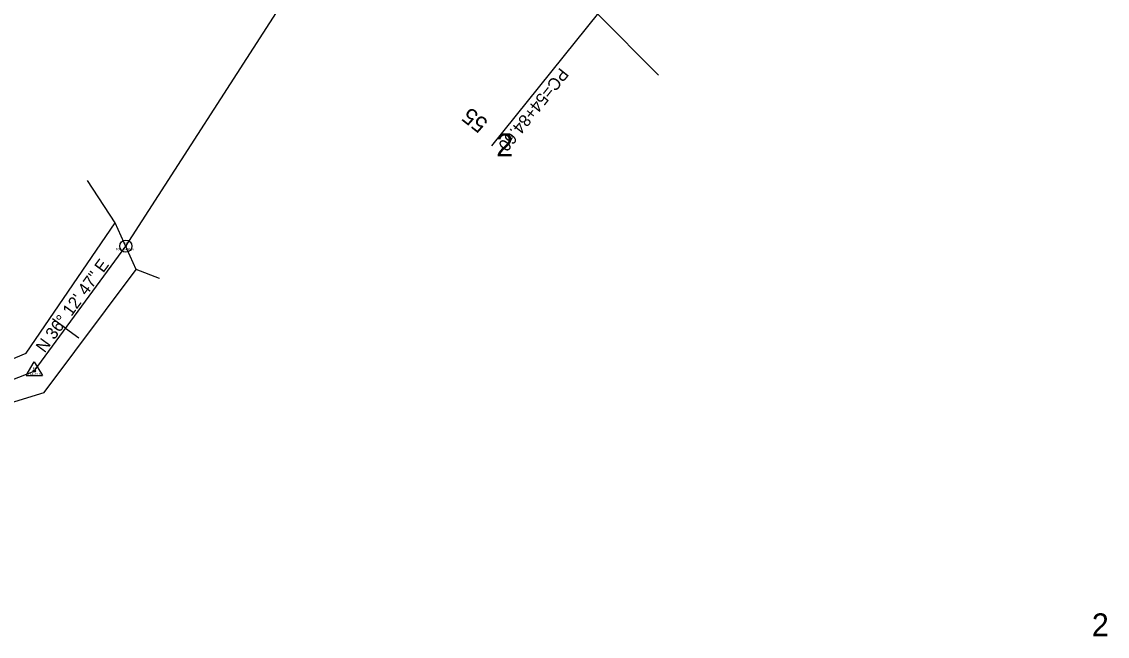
# Model space of a CAD drawing. Extents: x 2519952 to 2531965, y 848341 to 887632.
# Drawn here: x 2524841 to 2525378, y 870006 to 870310 of the extents above; entities that cross this region are included whole.
import ezdxf

# ---------------------------------------------------------------- set-up
doc = ezdxf.new("R2010")
doc.units = 0
for name, color, linetype in [('RD_EX_DV_Prop', 7, 'Continuous'), ('RD_EX_DV_TX_Prop', 7, 'Continuous'), ('RD_EX_H2O', 7, 'Continuous'), ('RD_EX_Misc', 7, 'Continuous'), ('RD_HC_Cl', 7, 'Continuous'), ('RD_HC_Data', 7, 'Continuous'), ('RD_HC_Data_Tic', 7, 'Continuous'), ('RD_HC_TX_Sta50', 7, 'Continuous'), ('RD_HC_txCode', 7, 'Continuous'), ('RD_SMD_Locator', 7, 'Continuous')]:
    doc.layers.add(name, color=color, linetype=linetype)

msp = doc.modelspace()

# ---------------------------------------------------------------- linework, layer by layer
at = {"layer": 'RD_EX_DV_Prop'}
for p, q in [((2524892.07, 870199.11), (2525017.12, 870393.04)), ((2525125.39, 870313.94), (2525155.58, 870283.69)), ((2524846.85, 870137.35), (2524892.07, 870199.11)), ((2524733.7, 870092.86), (2524846.85, 870137.35))]:
    msp.add_line(p, q, dxfattribs=at)
at = {"layer": 'RD_EX_H2O'}
for points in [[(2524730.38, 870097.59), (2524734.56, 870100.97), (2524750.79, 870106.68), (2524785.83, 870122.28), (2524842.84, 870146.18), (2524886.85, 870210.7)], [(2524788.68, 870107.35), (2524851.68, 870126.7), (2524897.24, 870187.62)]]:
    msp.add_lwpolyline(points, dxfattribs=at)
at = {"layer": 'RD_EX_Misc'}
msp.add_lwpolyline([(2524908.82, 870183.07), (2524897.24, 870187.62), (2524886.85, 870210.7), (2524873.11, 870231.59)], dxfattribs=at)
at = {"layer": 'RD_HC_Cl'}
for p, q in [((2524846.85, 870137.35), (2524892.07, 870199.11)), ((2524733.7, 870092.86), (2524846.85, 870137.35))]:
    msp.add_line(p, q, dxfattribs=at)
at = {"layer": 'RD_HC_Data'}
for p, q in [((2525146.04, 870339.68), (2525073.01, 870248.67)), ((2524842.88, 870135.06), (2524846.85, 870141.94)), ((2524846.85, 870141.94), (2524850.82, 870135.06)), ((2524842.88, 870135.06), (2524850.82, 870135.06))]:
    msp.add_line(p, q, dxfattribs=at)
for centre, radius in [((2524892.07, 870199.11), 3), ((2524892.07, 870199.11), 0.282), ((2524846.85, 870137.35), 0.529)]:
    msp.add_circle(centre, radius, dxfattribs=at)
at = {"layer": 'RD_HC_Data_Tic'}
for q in [(2524855.88, 870163.23), (2524868.79, 870153.78)]:
    msp.add_line((2524862.34, 870158.5), q, dxfattribs=at)
at = {"layer": 'RD_SMD_Locator'}
for centre in [(2524873.11, 870231.59), (2524886.85, 870210.7), (2524886.85, 870210.7), (2524892.07, 870199.11), (2524897.24, 870187.62), (2524897.24, 870187.62), (2524908.82, 870183.07), (2524842.84, 870146.18), (2524846.85, 870137.35), (2524851.68, 870126.7)]:
    msp.add_circle(centre, 0.001, dxfattribs=at)

# ---------------------------------------------------------------- texts
at = {"layer": 'RD_EX_DV_TX_Prop'}
for p in [(2525075.27, 870243.46), (2525369.86, 870006.15)]:
    msp.add_text('2', height=11.32, dxfattribs=at).set_placement(p)
at = {"layer": 'RD_HC_Data'}
for s, rotation, p in [('PC=54+84.60', 231.2529, (2525106.92, 870287.73)), ('N 36%%d 12\' 47" E', 53.787, (2524851.94, 870146))]:
    msp.add_text(s, height=6, rotation=rotation, dxfattribs=at).set_placement(p)
at = {"layer": 'RD_HC_TX_Sta50'}
msp.add_text('55', height=8, rotation=141.8357, dxfattribs=at).set_placement((2525071.78, 870260.78))
at = {"layer": 'RD_HC_txCode'}
for s, p in [('POT 15+50.33', (2524887.12, 870197.11)), ('43', (2524891.34, 870200.11)), ('42', (2524846.12, 870138.35)), ('PI 14+73.78', (2524843.07, 870135.35))]:
    msp.add_text(s, height=1, dxfattribs=at).set_placement(p)

doc.saveas('drawing.dxf')
